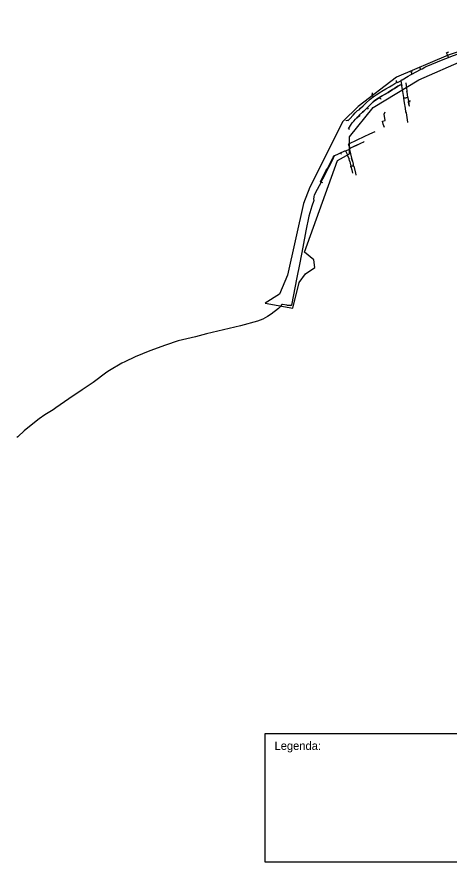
# Model space of a CAD drawing. Extents: x -743997 to -742329, y -1028103 to -1026437.
# Drawn here: x -743997 to -743217, y -1028103 to -1026577 of the extents above; entities that cross this region are included whole.
import ezdxf

# ---------------------------------------------------------------- set-up
doc = ezdxf.new("R2010")
doc.units = 0
doc.layers.add('Vrstva 1', color=7, linetype='Continuous')
doc.layers.add('Vrstva 63', color=7, linetype='Continuous')

msp = doc.modelspace()

# ---------------------------------------------------------------- linework, layer by layer
at = {"layer": 'Vrstva 1'}
for points in [[(-743217.82, -1026649.92), (-743210.62, -1026647.09), (-743198.6, -1026643.06), (-743187.59, -1026639.57), (-743182.72, -1026638.06), (-743178.99, -1026637.05), (-743168.05, -1026633.99), (-743149.31, -1026628.89), (-743142.03, -1026626.84), (-743136.8, -1026625.09), (-743134.26, -1026623.49), (-743132.37, -1026621.13), (-743130.99, -1026617.32), (-743130.73, -1026616.02), (-743131.26, -1026614.23), (-743135.12, -1026604.48), (-743136.11, -1026602.36), (-743139.36, -1026593.56), (-743143.13, -1026583.89), (-743145.51, -1026578.8), (-743146.51, -1026576.88)], [(-743268.33, -1026672.13), (-743265.33, -1026670.43), (-743260.13, -1026667.73), (-743256.54, -1026665.95), (-743251.66, -1026663.77), (-743247.87, -1026662.18), (-743237.56, -1026657.86), (-743227.2, -1026653.55), (-743217.82, -1026649.92)], [(-743217.82, -1026649.92), (-743218.22, -1026648.5), (-743219.45, -1026645.28), (-743220.88, -1026641.79), (-743218.89, -1026640.64), (-743216.86, -1026639.94)], [(-743220.88, -1026641.79), (-743218.89, -1026640.64)], [(-743219.45, -1026645.28), (-743220.88, -1026641.79)], [(-743218.22, -1026648.5), (-743219.45, -1026645.28)], [(-743218.89, -1026640.64), (-743216.86, -1026639.94)], [(-743217.82, -1026649.92), (-743218.22, -1026648.5)], [(-743268.957, -1026669.173), (-743269.354, -1026668.281), (-743268.052, -1026667.557), (-743268.109, -1026667.454)], [(-743265.33, -1026670.43), (-743260.13, -1026667.73)], [(-743256.54, -1026665.95), (-743251.66, -1026663.77)], [(-743302.02, -1026690.8), (-743301.43, -1026690.46), (-743290.65, -1026684.14), (-743285.95, -1026681.53), (-743283.52, -1026680.21)], [(-743290.65, -1026684.14), (-743285.95, -1026681.53)], [(-743285.061, -1026677.309), (-743285.288, -1026676.883), (-743283.324, -1026675.836), (-743283.39, -1026675.71)], [(-743285.288, -1026676.883), (-743283.324, -1026675.836)], [(-743285.061, -1026677.309), (-743284.46, -1026678.58), (-743283.52, -1026680.21)], [(-743283.52, -1026680.21), (-743268.33, -1026672.13)], [(-743269.47, -1026670.21), (-743268.957, -1026669.173)], [(-743269.47, -1026670.21), (-743268.33, -1026672.13)], [(-743353.49, -1026721.39), (-743347.83, -1026717.64), (-743339.97, -1026712.39), (-743337.63, -1026710.79), (-743330.82, -1026706.98), (-743323.98, -1026703.1), (-743318.32, -1026699.49), (-743310.96, -1026694.69), (-743311.11, -1026694.36)], [(-743343.97, -1026723.64), (-743338.79, -1026720.27), (-743331.76, -1026716.21), (-743326.53, -1026713.13), (-743318.54, -1026708.2), (-743314.77, -1026706.03), (-743308.87, -1026702.24), (-743303.98, -1026699.37), (-743302.11, -1026698.86)], [(-743318.32, -1026699.49), (-743310.96, -1026694.69)], [(-743312.12, -1026691.62), (-743311.94, -1026694.02), (-743311.11, -1026694.36)], [(-743312.12, -1026691.62), (-743311.94, -1026694.02)], [(-743311.94, -1026694.02), (-743311.11, -1026694.36)], [(-743311.11, -1026694.36), (-743310.7, -1026694.59), (-743309.6, -1026695.09), (-743303.79, -1026692.09)], [(-743311.11, -1026694.36), (-743310.7, -1026694.59), (-743309.6, -1026695.09)], [(-743309.6, -1026695.09), (-743303.79, -1026692.09)], [(-743302.98, -1026691.37), (-743303.79, -1026692.09)], [(-743303.79, -1026692.09), (-743302.98, -1026691.37)], [(-743303.79, -1026692.09), (-743302.11, -1026698.86)], [(-743303.79, -1026692.09), (-743302.11, -1026698.86)], [(-743301.55, -1026701.4), (-743301.75, -1026698.65), (-743303.15, -1026691.72), (-743302.98, -1026691.37)], [(-743301.75, -1026698.65), (-743303.15, -1026691.72)], [(-743302.98, -1026691.37), (-743302.85, -1026691.02), (-743302.44, -1026690.92)], [(-743302.98, -1026691.37), (-743302.44, -1026690.92)], [(-743302.44, -1026690.92), (-743302.02, -1026690.8)], [(-743302.11, -1026698.86), (-743301.55, -1026701.4)], [(-743293.69, -1026696.31), (-743294.82, -1026696.51), (-743293.6, -1026704.72), (-743292.64, -1026711)], [(-743354.82, -1026714.06), (-743355.48, -1026714.59), (-743355.65, -1026718.5), (-743354.2, -1026720.44), (-743353.49, -1026721.39)], [(-743347.83, -1026717.64), (-743339.97, -1026712.39)], [(-743339.97, -1026712.39), (-743337.63, -1026710.79)], [(-743337.63, -1026710.79), (-743330.82, -1026706.98)], [(-743326.53, -1026713.13), (-743331.76, -1026716.21)], [(-743330.82, -1026706.98), (-743323.98, -1026703.1)], [(-743318.54, -1026708.2), (-743326.53, -1026713.13)], [(-743323.98, -1026703.1), (-743318.32, -1026699.49)], [(-743314.77, -1026706.03), (-743318.54, -1026708.2)], [(-743308.87, -1026702.24), (-743314.77, -1026706.03)], [(-743303.98, -1026699.37), (-743308.87, -1026702.24)], [(-743298.27, -1026722.14), (-743299.92, -1026711.47), (-743301.55, -1026701.4)], [(-743292.64, -1026711), (-743291.47, -1026710.83)], [(-743290.96, -1026722.6), (-743291.62, -1026716.97), (-743292.45, -1026712.48), (-743292.64, -1026711)], [(-743291.62, -1026716.97), (-743292.45, -1026712.48)], [(-743402.86, -1026764.51), (-743402, -1026764), (-743400.03, -1026763.36), (-743398.93, -1026763.85), (-743398.4, -1026764.15), (-743395.54, -1026760.9), (-743389.79, -1026754.36), (-743385.78, -1026750.34), (-743381.78, -1026745.74), (-743379.03, -1026744.51), (-743376.13, -1026741.85), (-743371.78, -1026737.48), (-743366.92, -1026732.55), (-743358.79, -1026725.16), (-743356.25, -1026723.43), (-743353.49, -1026721.39)], [(-743366.92, -1026732.55), (-743358.79, -1026725.16)], [(-743358.79, -1026725.16), (-743356.25, -1026723.43)], [(-743356.25, -1026723.43), (-743353.49, -1026721.39)], [(-743353.49, -1026721.39), (-743347.83, -1026717.64)], [(-743353.25, -1026730.06), (-743350.52, -1026727.93), (-743343.97, -1026723.64)], [(-743350.52, -1026727.93), (-743353.25, -1026730.06)], [(-743343.97, -1026723.64), (-743350.52, -1026727.93)], [(-743338.79, -1026720.27), (-743343.97, -1026723.64)], [(-743339.12, -1026725.92), (-743339.55, -1026724.99), (-743341.92, -1026723.68), (-743342.61, -1026723.02), (-743343.97, -1026723.64)], [(-743331.76, -1026716.21), (-743338.79, -1026720.27)], [(-743299.54, -1026722.34), (-743298.27, -1026722.14)], [(-743298.03, -1026723.69), (-743298.27, -1026722.14)], [(-743290.96, -1026722.6), (-743297.71, -1026723.63), (-743298.03, -1026723.69)], [(-743291.33, -1026767.54), (-743290.68, -1026766.7), (-743291.98, -1026758.39), (-743293.37, -1026750.13), (-743294.28, -1026748.02), (-743295.24, -1026741.5), (-743296.69, -1026732.22), (-743298.03, -1026723.69)], [(-743297.71, -1026723.63), (-743290.96, -1026722.6)], [(-743290.96, -1026722.6), (-743290.77, -1026722.7), (-743289.64, -1026729.86)], [(-743289.64, -1026729.86), (-743288.56, -1026729.67), (-743286.98, -1026729.62), (-743287.06, -1026727.55)], [(-743286.98, -1026729.62), (-743287.06, -1026727.55)], [(-743381.78, -1026745.74), (-743379.03, -1026744.51)], [(-743379.03, -1026744.51), (-743376.13, -1026741.85)], [(-743378.78, -1026754.56), (-743372.83, -1026748.67), (-743370.65, -1026747), (-743368.18, -1026744.74), (-743366.72, -1026743.45), (-743366.01, -1026742.69), (-743365.78, -1026742.49), (-743364.24, -1026741.3)], [(-743376.13, -1026741.85), (-743371.78, -1026737.48)], [(-743371.78, -1026737.48), (-743366.92, -1026732.55)], [(-743366.72, -1026743.45), (-743368.18, -1026744.74), (-743370.65, -1026747)], [(-743365.78, -1026742.49), (-743366.01, -1026742.69), (-743366.72, -1026743.45)], [(-743358.26, -1026735.14), (-743358.69, -1026735.59), (-743360.18, -1026736.84), (-743364.09, -1026741.15), (-743364.24, -1026741.3)], [(-743364.24, -1026741.3), (-743362.66, -1026743.2)], [(-743364.24, -1026741.3), (-743362.66, -1026743.2)], [(-743360.18, -1026736.84), (-743364.09, -1026741.15)], [(-743358.26, -1026735.14), (-743358.69, -1026735.59)], [(-743353.25, -1026730.06), (-743356.84, -1026733.43), (-743358.26, -1026735.14)], [(-743356.84, -1026733.43), (-743358.26, -1026735.14)], [(-743353.25, -1026730.06), (-743356.84, -1026733.43)], [(-743353.25, -1026730.06), (-743352.82, -1026730.47)], [(-743352.82, -1026730.47), (-743353.25, -1026730.06)], [(-743289.64, -1026729.86), (-743288.56, -1026729.67)], [(-743287.21, -1026738.25), (-743288.22, -1026738.31), (-743288.99, -1026734.18), (-743289.6, -1026730.29), (-743289.64, -1026729.86)], [(-743289.6, -1026730.29), (-743288.99, -1026734.18)], [(-743288.56, -1026729.67), (-743286.98, -1026729.62)], [(-743396.11, -1026780.09), (-743398.07, -1026779.12), (-743394.64, -1026772.67), (-743391.23, -1026768.13), (-743388.63, -1026765.11), (-743385.67, -1026761.62), (-743382.94, -1026759.25), (-743379, -1026755.24), (-743378.78, -1026754.56)], [(-743395.54, -1026760.9), (-743389.79, -1026754.36)], [(-743389.79, -1026754.36), (-743385.78, -1026750.34)], [(-743385.78, -1026750.34), (-743381.78, -1026745.74)], [(-743379, -1026755.24), (-743382.94, -1026759.25)], [(-743377.18, -1026756.39), (-743378.78, -1026754.56)], [(-743370.65, -1026747), (-743372.83, -1026748.67)], [(-743333.37, -1026776.56), (-743335.29, -1026770.28), (-743336.41, -1026765), (-743331.95, -1026764.12), (-743333.78, -1026752.76), (-743331.94, -1026748.26)], [(-743333.78, -1026752.76), (-743331.94, -1026748.26)], [(-743331.95, -1026764.12), (-743333.78, -1026752.76)], [(-743398.93, -1026763.85), (-743398.4, -1026764.15)], [(-743398.4, -1026764.15), (-743395.54, -1026760.9)], [(-743388.63, -1026765.11), (-743391.23, -1026768.13)], [(-743395.44, -1026814.84), (-743395.16, -1026814.48), (-743394.9, -1026813.96), (-743397.38, -1026808.56), (-743397.97, -1026807.02), (-743397.52, -1026806.15), (-743382.54, -1026799.04), (-743370.06, -1026792.87), (-743359.43, -1026787.9), (-743350.11, -1026783.57)], [(-743370.06, -1026792.87), (-743359.43, -1026787.9)], [(-743381.88, -1026807.98), (-743375.64, -1026805.08), (-743370.46, -1026802.34), (-743369.62, -1026802.11)], [(-743375.64, -1026805.08), (-743370.46, -1026802.34)], [(-743412.57, -1026822.39), (-743405.73, -1026819.1)], [(-743405.73, -1026819.1), (-743404.69, -1026818.67), (-743403.64, -1026818.83)], [(-743405.73, -1026819.1), (-743403.64, -1026818.83)], [(-743403.64, -1026818.83), (-743403.12, -1026818.81), (-743396.24, -1026815.55), (-743395.44, -1026814.84)], [(-743403.64, -1026818.83), (-743400.74, -1026824.97), (-743399.62, -1026827.66), (-743397.03, -1026833.38)], [(-743403.12, -1026818.81), (-743396.24, -1026815.55)], [(-743394.9, -1026813.96), (-743397.38, -1026808.56)], [(-743396.24, -1026816.43), (-743395.44, -1026814.84)], [(-743395.44, -1026814.84), (-743396.24, -1026816.43), (-743392.39, -1026832.06), (-743390.95, -1026837.66), (-743389.55, -1026843.06)], [(-743381.88, -1026807.98), (-743388.29, -1026810.99), (-743394.18, -1026813.84), (-743395.44, -1026814.84)], [(-743395.44, -1026814.84), (-743394.18, -1026813.84)], [(-743388.29, -1026810.99), (-743381.88, -1026807.98)], [(-743381.43, -1026808.95), (-743381.88, -1026807.98)], [(-743447.61, -1026875.1), (-743448.5, -1026874.64), (-743445.94, -1026869.25), (-743442.04, -1026861.39), (-743438.68, -1026854.88), (-743436.63, -1026851.36), (-743435.36, -1026849.91), (-743433.98, -1026847.25), (-743429.97, -1026838.4), (-743425.44, -1026830.39), (-743424.05, -1026827.64), (-743423.08, -1026827.2)], [(-743423.08, -1026827.2), (-743425.97, -1026831.9), (-743426.43, -1026833.64), (-743434.1, -1026848.86), (-743444.82, -1026869.79), (-743447.45, -1026874.82), (-743447.61, -1026875.1)], [(-743423.08, -1026827.2), (-743418.74, -1026825.29), (-743412.57, -1026822.39)], [(-743410.45, -1026824.77), (-743411.44, -1026824.16), (-743411.95, -1026823.63), (-743412.57, -1026822.39)], [(-743399.62, -1026827.66), (-743397.03, -1026833.38)], [(-743397.03, -1026833.38), (-743397.169, -1026834.047), (-743396.209, -1026837.6), (-743395.87, -1026837.887)], [(-743390.95, -1026837.66), (-743392.39, -1026832.06)], [(-743395.87, -1026837.887), (-743395.12, -1026840.8), (-743393.79, -1026846.53), (-743393.7, -1026846.75)], [(-743395.26, -1026846.88), (-743393.7, -1026846.75)], [(-743395.12, -1026840.8), (-743393.79, -1026846.53)], [(-743389.03, -1026845.5), (-743393.53, -1026846.58), (-743393.7, -1026846.75)], [(-743393.7, -1026846.75), (-743392.31, -1026853.17), (-743390.9, -1026858.76)], [(-743393.53, -1026846.58), (-743389.03, -1026845.5)], [(-743389.55, -1026843.06), (-743388.46, -1026842.83)], [(-743389.03, -1026845.5), (-743389.19, -1026844.28), (-743389.55, -1026843.06)], [(-743389.03, -1026845.5), (-743388.69, -1026846.44), (-743385.51, -1026858.74), (-743384.73, -1026861.96), (-743383.69, -1026861.71)], [(-743447.61, -1026875.1), (-743454.75, -1026888.82), (-743456.35, -1026891.87), (-743460.04, -1026898.91), (-743460.46, -1026901.28)], [(-743448.5, -1026874.64), (-743445.94, -1026869.25)], [(-743447.61, -1026875.1), (-743446.73, -1026875.56), (-743444.9, -1026875.83)], [(-743447.45, -1026874.82), (-743444.82, -1026869.79)], [(-743456.35, -1026891.87), (-743454.75, -1026888.82)], [(-743460.9, -1026908.48), (-743464.19, -1026918.38), (-743469.53, -1026936.71), (-743474.81, -1026962.9), (-743480.62, -1026992.61), (-743485.86, -1027021.05), (-743491.9, -1027050.7), (-743497.42, -1027078.84), (-743500.69, -1027097.58), (-743501.39, -1027098.25), (-743503.3, -1027097.96), (-743509.52, -1027097.37), (-743517.16, -1027096.24), (-743518.32, -1027096.28), (-743519.12, -1027097), (-743521.03, -1027099.84), (-743524.69, -1027103.26), (-743537.44, -1027113.43), (-743544.21, -1027118), (-743552.54, -1027122.58), (-743562.58, -1027126.07), (-743592.87, -1027134.55), (-743623.36, -1027141.74), (-743654.22, -1027149.09), (-743674.27, -1027154.39), (-743705.24, -1027161.82), (-743728.48, -1027169.62), (-743756.49, -1027180.1), (-743783.21, -1027190.47), (-743801.94, -1027199.43), (-743807.19, -1027202.17), (-743829.31, -1027215.3), (-743834.28, -1027218.54), (-743859.02, -1027236.81), (-743878.6, -1027250.08), (-743902.83, -1027266.5), (-743926.16, -1027282.75), (-743931.04, -1027286.15), (-743945.98, -1027295.42), (-743956.23, -1027302.75), (-743979.75, -1027321.42), (-743983.17, -1027324.35), (-743984.69, -1027325.73), (-743993.34, -1027333.52), (-743995.02, -1027335.04), (-743996.52, -1027336.1)], [(-743460.46, -1026901.28), (-743460.78, -1026902.52), (-743461.08, -1026905.36), (-743460.9, -1026908.48)], [(-743509.52, -1027097.37), (-743503.3, -1027097.96)]]:
    msp.add_lwpolyline(points, dxfattribs=at)
msp.add_lwpolyline([(-743548.62, -1027870.911), (-742328.6, -1027870.911), (-742328.6, -1028102.98), (-743548.62, -1028102.98)], close=True, dxfattribs=at)
at = {"layer": 'Vrstva 63'}
msp.add_lwpolyline([(-743138.65, -1026619.32), (-743218.02, -1026645.78), (-743311.16, -1026685.46), (-743380.48, -1026738.91), (-743408.52, -1026765.9), (-743467.79, -1026884.43), (-743479.43, -1026914.06), (-743508.01, -1027043.18), (-743522.82, -1027077.58), (-743548.62, -1027093.98), (-743548.62, -1027093.98), (-743498.48, -1027102.98), (-743487.37, -1027056.41), (-743475.73, -1027040.53), (-743458.66, -1027029.16), (-743460.38, -1027015.66), (-743477.18, -1027001.38), (-743417.65, -1026836.01), (-743396.48, -1026824.1), (-743396.48, -1026793.68), (-743353.56, -1026740.36), (-743271.14, -1026690.36), (-743188.72, -1026654.24)], dxfattribs=at)

# ---------------------------------------------------------------- texts
at = {"layer": 'Vrstva 1'}
msp.add_text('Legenda:', height=15, dxfattribs=at).set_placement((-743531.463, -1027900.394))

doc.saveas('drawing.dxf')
